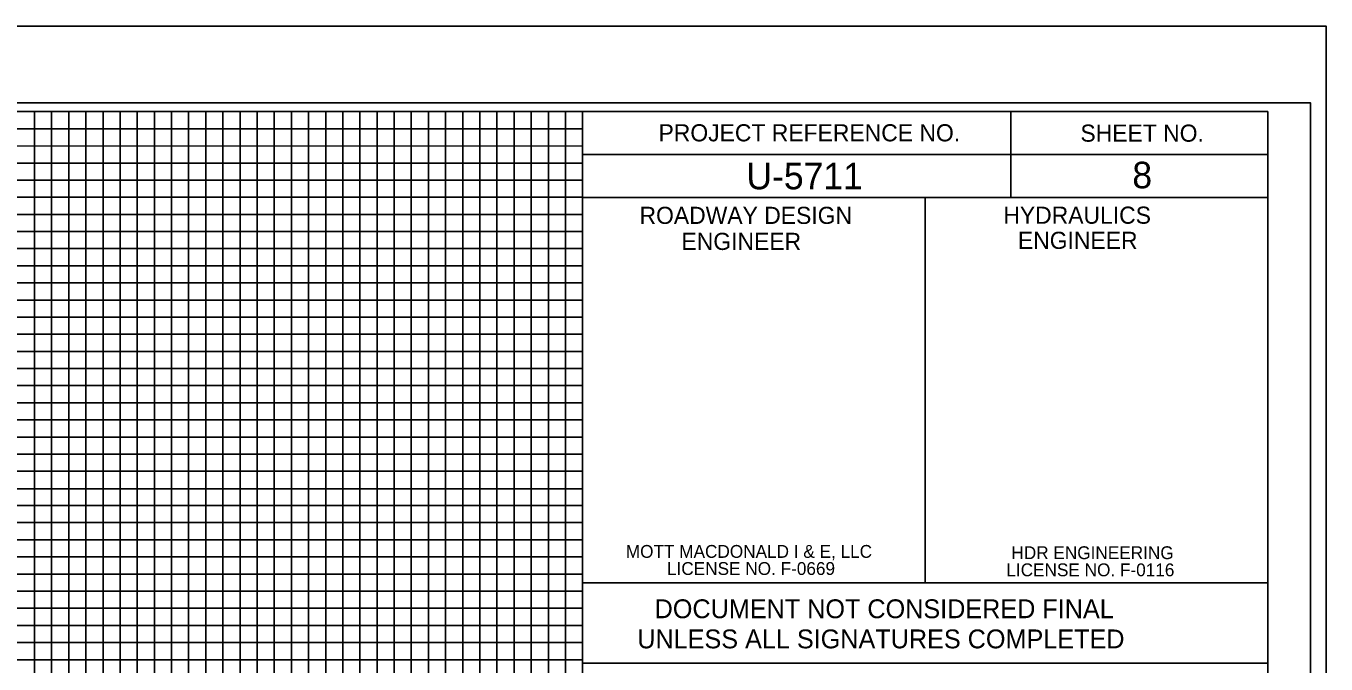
# Model space of a CAD drawing. Extents: x 1754992 to 1757273, y 732111 to 735411.
# Drawn here: x 1756485.2 to 1756864.7, y 735224.5 to 735410.8 of the extents above; entities that cross this region are included whole.
import ezdxf

# ---------------------------------------------------------------- set-up
doc = ezdxf.new("R2010")
doc.units = 0
for name, color, linetype in [('Old_Level_3', 7, 'Continuous'), ('Old_Level_42', 7, 'Continuous'), ('Old_Level_45', 7, 'Continuous'), ('Scratch_Level_3', 7, 'Continuous'), ('Sheet Cutting Line CELL', 7, 'Continuous'), ('Sheet Data Field CELL', 7, 'Continuous'), ('Sheet DOT Grid CELL', 7, 'Continuous'), ('Sheet Plot Border Inside CELL', 7, 'Continuous'), ('Sheet Plot Border Outside CELL', 7, 'Continuous'), ('Sheet Profile CELL', 7, 'Continuous'), ('Sheet Profile Grid Major CELL', 7, 'Continuous'), ('Sheet Profile Grid Middle CELL', 7, 'Continuous'), ('Sheet Profile Grid Minor CELL', 7, 'Continuous'), ('Sheet Sticker Exception Certification CELL', 7, 'Continuous')]:
    doc.layers.add(name, color=color, linetype=linetype)

msp = doc.modelspace()

# ---------------------------------------------------------------- linework, layer by layer
at = {"layer": 'Old_Level_42'}
msp.add_line((1756647.62, 735224.73), (1756647.62, 735248.23), dxfattribs=at)
msp.add_lwpolyline([(1756847.67, 735189.43), (1756647.62, 735189.43), (1756647.62, 735224.73)], dxfattribs=at)
at = {"layer": 'Scratch_Level_3'}
msp.add_lwpolyline([(1755397.67, 734885.78), (1755397.67, 735385.78), (1756647.62, 735385.78), (1756647.63, 735152.66), (1756797.67, 735152.66), (1756797.67, 734885.78)], close=True, dxfattribs=at)
at = {"layer": 'Sheet Cutting Line CELL'}
msp.add_line((1756864.67, 735410.78), (1755180.67, 735410.78), dxfattribs=at)
at = {"layer": 'Sheet DOT Grid CELL'}
for p, q in [((1756497.67, 734885.78), (1756497.67, 735385.78)), ((1756547.67, 734885.78), (1756547.67, 735385.78)), ((1756597.67, 734885.78), (1756597.67, 735385.78)), ((1756647.62, 735335.78), (1755347.67, 735335.78)), ((1756647.62, 735285.78), (1755347.67, 735285.78)), ((1756647.67, 734885.78), (1756647.67, 735248.23)), ((1756647.67, 735235.78), (1755347.67, 735235.78))]:
    msp.add_line(p, q, dxfattribs=at)
at = {"layer": 'Sheet Plot Border Inside CELL'}
msp.add_lwpolyline([(1755193.67, 734333.23), (1756860.17, 734333.23), (1756860.17, 735388.33), (1755193.67, 735388.33)], close=True, dxfattribs=at)
at = {"layer": 'Sheet Plot Border Outside CELL'}
msp.add_lwpolyline([(1755180.67, 734310.78), (1756864.67, 734310.78), (1756864.67, 735410.78), (1755180.67, 735410.78)], close=True, dxfattribs=at)
at = {"layer": 'Sheet Profile CELL'}
for p, q in [((1756772.67, 735385.73), (1756772.67, 735360.73)), ((1756647.62, 735373.23), (1756847.67, 735373.23)), ((1756747.67, 735360.73), (1756747.67, 735248.28))]:
    msp.add_line(p, q, dxfattribs=at)
for points in [[(1756847.67, 735385.78), (1755347.67, 735385.78), (1755347.67, 734335.78), (1756847.67, 734335.78)], [(1756647.62, 735385.78), (1756847.67, 735385.78), (1756847.67, 735360.73), (1756647.62, 735360.73)], [(1756647.62, 735360.73), (1756747.67, 735360.73), (1756747.67, 735248.23), (1756647.62, 735248.23)], [(1756747.67, 735360.73), (1756847.67, 735360.73), (1756847.67, 735248.23), (1756747.67, 735248.23)]]:
    msp.add_lwpolyline(points, close=True, dxfattribs=at)
at = {"layer": 'Sheet Profile Grid Major CELL'}
for points in [[(1756097.67, 734885.78), (1756147.67, 734885.78), (1756147.67, 735385.78), (1756197.67, 735385.78), (1756197.67, 734885.78), (1756247.67, 734885.78), (1756247.67, 735385.78), (1756297.67, 735385.78), (1756297.67, 734885.78), (1756347.67, 734885.78), (1756347.67, 735385.78), (1756397.67, 735385.78), (1756397.67, 734885.78), (1756447.67, 734885.78), (1756447.67, 735385.78), (1756497.67, 735385.78), (1756497.67, 734885.78), (1756547.67, 734885.78), (1756547.67, 735385.78), (1756597.67, 735385.78), (1756597.67, 734885.78), (1756647.67, 734885.78), (1756647.67, 735385.78), (1756673.97, 735385.78)], [(1755347.67, 735335.78), (1756647.67, 735335.78)], [(1756647.67, 735285.78), (1755347.67, 735285.78), (1755347.67, 735235.78), (1756647.67, 735235.78)], [(1756797.67, 735152.66), (1756797.67, 734885.78), (1756847.67, 734885.78), (1756847.67, 735235.78)]]:
    msp.add_lwpolyline(points, dxfattribs=at)
at = {"layer": 'Sheet Profile Grid Middle CELL'}
msp.add_line((1755347.67, 735360.78), (1756647.62, 735360.78), dxfattribs=at)
for points in [[(1756122.67, 734885.78), (1756172.67, 734885.78), (1756172.67, 735385.78), (1756222.67, 735385.78), (1756222.67, 734885.78), (1756272.67, 734885.78), (1756272.67, 735385.78), (1756322.67, 735385.78), (1756322.67, 734885.78), (1756372.67, 734885.78), (1756372.67, 735385.78), (1756422.67, 735385.78), (1756422.67, 734885.78), (1756472.67, 734885.78), (1756472.67, 735385.78), (1756522.67, 735385.78), (1756522.67, 734885.78), (1756572.67, 734885.78), (1756572.67, 735385.78), (1756622.67, 735385.78), (1756622.67, 734885.78), (1756672.67, 734885.78), (1756672.67, 735152.66)], [(1756647.67, 735310.78), (1755347.67, 735310.78), (1755347.67, 735260.78), (1756647.67, 735260.78)]]:
    msp.add_lwpolyline(points, dxfattribs=at)
at = {"layer": 'Sheet Profile Grid Minor CELL'}
for p, q in [((1755397.67, 735380.78), (1756647.67, 735380.78)), ((1756647.67, 735375.78), (1755397.67, 735375.43)), ((1755397.67, 735370.78), (1756647.67, 735370.78)), ((1756647.62, 735250.78), (1755397.67, 735250.78)), ((1756647.67, 735245.78), (1755397.67, 735245.78)), ((1756647.67, 735240.78), (1755397.67, 735240.78)), ((1755397.67, 735230.78), (1756647.67, 735230.78)), ((1756647.67, 735225.78), (1755397.67, 735225.78))]:
    msp.add_line(p, q, dxfattribs=at)
for points in [[(1756482.67, 735385.78), (1756487.67, 735385.78), (1756487.67, 734885.78), (1756492.67, 734885.78), (1756492.67, 735385.78), (1756502.67, 735385.78), (1756502.67, 734885.78), (1756507.67, 734885.78), (1756507.67, 735385.78), (1756512.67, 735385.78), (1756512.67, 734885.78), (1756517.67, 734885.78), (1756517.67, 735385.78), (1756527.67, 735385.78), (1756527.67, 734885.78), (1756532.67, 734885.78), (1756532.67, 735385.78), (1756537.67, 735385.78), (1756537.67, 734885.78)], [(1756542.67, 734885.78), (1756542.67, 735385.78), (1756552.67, 735385.78), (1756552.67, 734885.78)], [(1756557.67, 734885.78), (1756557.67, 735385.78), (1756562.67, 735385.78), (1756562.67, 734885.78)], [(1756567.67, 734885.78), (1756567.67, 735385.78), (1756577.67, 735385.78), (1756577.67, 734885.78)], [(1756582.67, 734885.78), (1756582.67, 735385.78), (1756587.67, 735385.78), (1756587.67, 734885.78)], [(1756592.67, 734885.78), (1756592.67, 735385.78), (1756602.67, 735385.78), (1756602.67, 734885.78)], [(1756607.67, 734885.78), (1756607.67, 735385.78), (1756612.67, 735385.78), (1756612.67, 734885.78)], [(1756617.67, 734885.78), (1756617.67, 735385.78), (1756627.67, 735385.78), (1756627.67, 734885.78)], [(1756632.67, 734885.78), (1756632.67, 735385.78), (1756637.67, 735385.78), (1756637.67, 734885.78)], [(1756642.67, 734885.78), (1756642.67, 735385.78), (1756652.67, 735385.78)], [(1756647.67, 735365.78), (1755397.67, 735365.78), (1755397.67, 735355.78), (1756647.67, 735355.78)], [(1756647.62, 735350.78), (1755397.67, 735350.78), (1755397.67, 735345.78), (1756647.67, 735345.78)], [(1756647.67, 735340.78), (1755397.67, 735340.78), (1755397.67, 735330.78), (1756647.67, 735330.78)], [(1756647.67, 735325.78), (1755397.67, 735325.78), (1755397.67, 735320.78), (1756647.67, 735320.78)], [(1756647.67, 735315.78), (1755397.67, 735315.78), (1755397.67, 735305.78), (1756647.67, 735305.78)], [(1756647.67, 735300.78), (1755397.67, 735300.78), (1755397.67, 735295.78), (1756647.67, 735295.78)], [(1756647.67, 735290.78), (1755397.67, 735290.78), (1755397.67, 735280.78), (1756647.67, 735280.78)], [(1756647.67, 735275.68), (1755397.77, 735275.68), (1755397.77, 735270.78), (1756647.67, 735270.78)], [(1756647.67, 735265.78), (1755397.67, 735265.78), (1755397.67, 735255.78), (1756647.67, 735255.78)]]:
    msp.add_lwpolyline(points, dxfattribs=at)
at = {"layer": 'Sheet Sticker Exception Certification CELL'}
for p, q in [((1756647.62, 735224.73), (1756647.62, 735248.23)), ((1756647.62, 735248.23), (1756847.66, 735248.23)), ((1756647.62, 735224.73), (1756647.62, 735248.23)), ((1756647.62, 735248.23), (1756847.66, 735248.23)), ((1756847.66, 735248.22), (1756847.66, 735224.72)), ((1756847.66, 735248.22), (1756847.66, 735224.72)), ((1756847.66, 735224.73), (1756647.62, 735224.73)), ((1756847.66, 735224.73), (1756647.62, 735224.73))]:
    msp.add_line(p, q, dxfattribs=at)

# ---------------------------------------------------------------- texts
at = {"layer": 'Old_Level_3'}
for s, p in [('HDR ENGINEERING', (1756772.84, 735255.13)), (' LICENSE NO. F-0116', (1756769.97, 735250.13))]:
    msp.add_text(s, height=3.75, rotation=360, dxfattribs=at).set_placement(p)
at = {"layer": 'Old_Level_45'}
for s, p in [('MOTT MACDONALD I & E, LLC', (1756660.28, 735255.51)), (' LICENSE NO. F-0669', (1756670.91, 735250.51))]:
    msp.add_text(s, height=3.75, rotation=360, dxfattribs=at).set_placement(p)
at = {"layer": 'Sheet Data Field CELL'}
for s, p in [('U-5711', (1756695.48, 735363.1)), ('8', (1756808.14, 735363.4))]:
    msp.add_text(s, height=7.75, dxfattribs=at).set_placement(p)
at = {"layer": 'Sheet Profile CELL'}
for s, height, p in [('PROJECT REFERENCE NO.', 5.0001, (1756669.83, 735377.1)), ('SHEET NO.', 5, (1756792.98, 735377)), ('ROADWAY DESIGN', 5.0001, (1756664.28, 735353)), ('HYDRAULICS', 5, (1756770.48, 735353.05)), ('ENGINEER', 5, (1756676.53, 735345.4)), ('ENGINEER', 5, (1756774.73, 735345.7))]:
    msp.add_text(s, height=height, dxfattribs=at).set_placement(p)
at = {"layer": 'Sheet Sticker Exception Certification CELL'}
for s, p in [('DOCUMENT NOT CONSIDERED FINAL', (1756668.69, 735237.89)), ('DOCUMENT NOT CONSIDERED FINAL', (1756668.69, 735237.89)), ('UNLESS ALL SIGNATURES COMPLETED', (1756663.62, 735229.09)), ('UNLESS ALL SIGNATURES COMPLETED', (1756663.62, 735229.09))]:
    msp.add_text(s, height=5.5, dxfattribs=at).set_placement(p)

doc.saveas('drawing.dxf')
